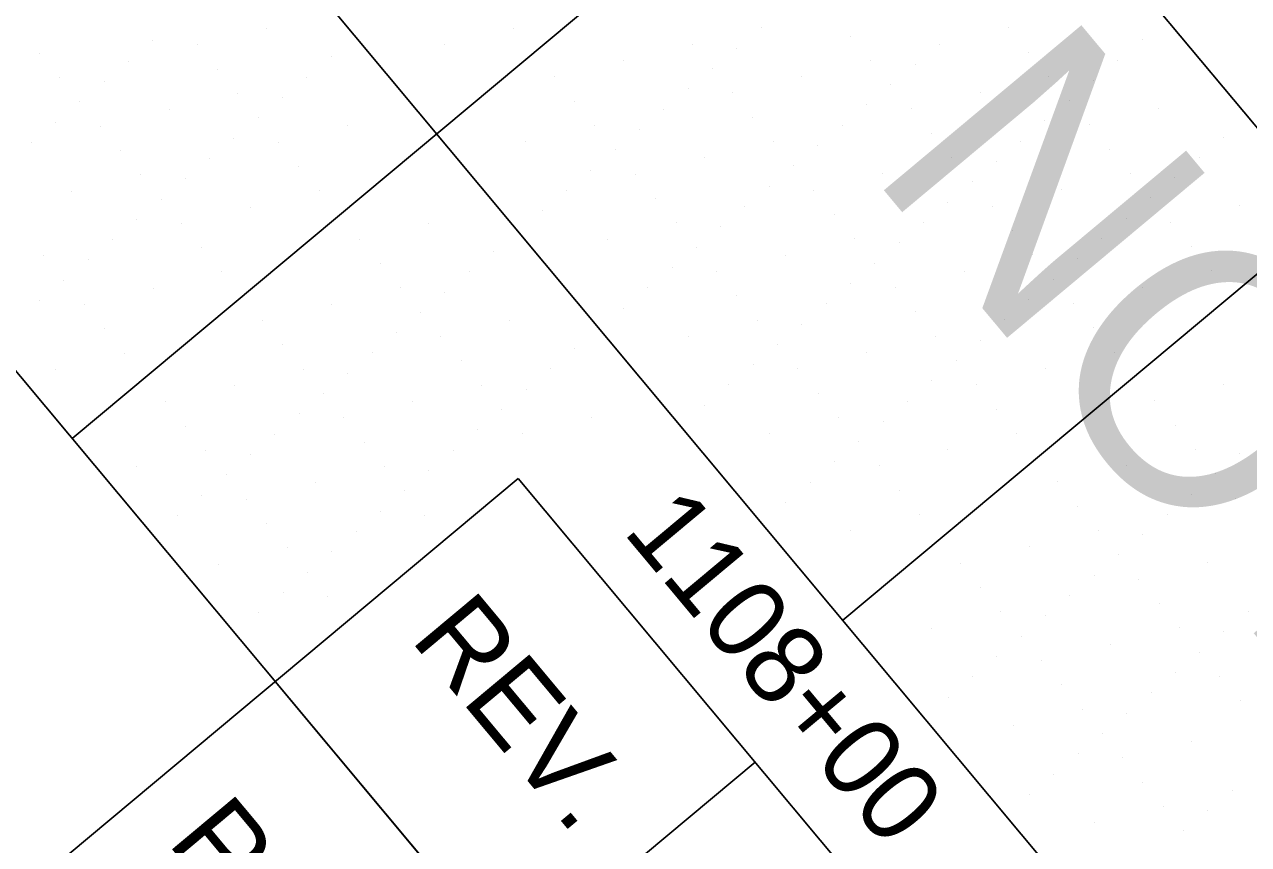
# Model space of a CAD drawing. Extents: x 2042995 to 2043795, y 305365 to 306249.
# Drawn here: x 2043381.75 to 2043420.4, y 305583.24 to 305609.13 of the extents above; entities that cross this region are included whole.
import ezdxf

# ---------------------------------------------------------------- set-up
doc = ezdxf.new("R2010")
doc.units = 0
for name, color, linetype in [('BR_BORDER LINES', 7, 'Continuous'), ('BR_CONCRETE', 7, 'Continuous'), ('BR_GRID DOTS', 7, 'Continuous'), ('BR_GRID LINES', 7, 'Continuous'), ('BR_TEXT', 7, 'Continuous')]:
    doc.layers.add(name, color=color, linetype=linetype)

msp = doc.modelspace()

# ---------------------------------------------------------------- linework, layer by layer
at = {"layer": 'BR_BORDER LINES'}
for p, q in [((2043360.173, 305623.692), (2043416.369, 305556.406)), ((2043355.121, 305559.541), (2043397.335, 305594.797)), ((2043397.335, 305594.797), (2043493.488, 305479.669)), ((2043389.659, 305588.387), (2043416.369, 305556.407)), ((2043404.813, 305585.843), (2043381.788, 305566.612))]:
    msp.add_line(p, q, dxfattribs=at)
at = {"layer": 'BR_CONCRETE'}
msp.add_spline([(2043139.109, 306017.548), (2043148.199, 306007.16), (2043160.233, 305993.368), (2043172.245, 305979.557), (2043184.234, 305965.727), (2043196.201, 305951.879), (2043208.145, 305938.012), (2043220.067, 305924.126), (2043231.966, 305910.221), (2043243.843, 305896.297), (2043255.698, 305882.355), (2043267.529, 305868.394), (2043279.339, 305854.414), (2043291.126, 305840.415), (2043302.89, 305826.398), (2043314.632, 305812.361), (2043326.352, 305798.306), (2043338.049, 305784.233), (2043349.724, 305770.14), (2043361.376, 305756.029), (2043373.005, 305741.899), (2043384.613, 305727.75), (2043396.197, 305713.582), (2043407.76, 305699.396), (2043419.299, 305685.191), (2043430.817, 305670.967), (2043442.311, 305656.724), (2043453.784, 305642.463), (2043465.234, 305628.182), (2043476.661, 305613.883), (2043488.066, 305599.566), (2043499.448, 305585.229), (2043510.808, 305570.874), (2043522.146, 305556.5), (2043533.461, 305542.107), (2043544.753, 305527.695), (2043547.219, 305524.543)], degree=3, dxfattribs=at)
at = {"layer": 'BR_GRID DOTS'}
for p, q in [((2043389.381, 305609), (2043389.381, 305609)), ((2043397.192, 305609.008), (2043397.192, 305609.008)), ((2043405.002, 305609.017), (2043405.002, 305609.017)), ((2043412.812, 305609.025), (2043412.812, 305609.025)), ((2043385.797, 305608.612), (2043385.797, 305608.612)), ((2043392.198, 305608.747), (2043392.198, 305608.747)), ((2043407.819, 305608.764), (2043407.819, 305608.764)), ((2043410.636, 305608.511), (2043410.636, 305608.511)), ((2043417.038, 305608.646), (2043417.038, 305608.646)), ((2043382.212, 305608.224), (2043382.212, 305608.224)), ((2043387.205, 305608.485), (2043387.205, 305608.485)), ((2043395.016, 305608.494), (2043395.016, 305608.494)), ((2043402.826, 305608.502), (2043402.826, 305608.502)), ((2043404.234, 305608.376), (2043404.234, 305608.376)), ((2043413.453, 305608.258), (2043413.453, 305608.258)), ((2043385.029, 305607.971), (2043385.029, 305607.971)), ((2043391.431, 305608.106), (2043391.431, 305608.106)), ((2043400.65, 305607.988), (2043400.65, 305607.988)), ((2043408.46, 305607.996), (2043408.46, 305607.996)), ((2043409.869, 305607.87), (2043409.869, 305607.87)), ((2043416.27, 305608.005), (2043416.27, 305608.005)), ((2043382.853, 305607.456), (2043382.853, 305607.456)), ((2043387.846, 305607.718), (2043387.846, 305607.718)), ((2043390.663, 305607.465), (2043390.663, 305607.465)), ((2043398.474, 305607.473), (2043398.474, 305607.473)), ((2043403.467, 305607.735), (2043403.467, 305607.735)), ((2043406.284, 305607.482), (2043406.284, 305607.482)), ((2043414.094, 305607.49), (2043414.094, 305607.49)), ((2043415.503, 305607.364), (2043415.503, 305607.364)), ((2043384.262, 305607.33), (2043384.262, 305607.33)), ((2043402.699, 305607.094), (2043402.699, 305607.094)), ((2043404.108, 305606.967), (2043404.108, 305606.967)), ((2043409.101, 305607.229), (2043409.101, 305607.229)), ((2043411.918, 305606.976), (2043411.918, 305606.976)), ((2043383.494, 305606.689), (2043383.494, 305606.689)), ((2043388.487, 305606.95), (2043388.487, 305606.95)), ((2043389.896, 305606.824), (2043389.896, 305606.824)), ((2043399.115, 305606.706), (2043399.115, 305606.706)), ((2043408.334, 305606.588), (2043408.334, 305606.588)), ((2043414.735, 305606.723), (2043414.735, 305606.723)), ((2043386.311, 305606.436), (2043386.311, 305606.436)), ((2043401.932, 305606.453), (2043401.932, 305606.453)), ((2043404.749, 305606.2), (2043404.749, 305606.2)), ((2043409.742, 305606.461), (2043409.742, 305606.461)), ((2043417.552, 305606.47), (2043417.552, 305606.47)), ((2043420.369, 305606.217), (2043420.369, 305606.217)), ((2043382.727, 305606.048), (2043382.727, 305606.048)), ((2043384.135, 305605.921), (2043384.135, 305605.921)), ((2043389.128, 305606.183), (2043389.128, 305606.183)), ((2043391.945, 305605.93), (2043391.945, 305605.93)), ((2043399.756, 305605.938), (2043399.756, 305605.938)), ((2043401.164, 305605.812), (2043401.164, 305605.812)), ((2043407.566, 305605.947), (2043407.566, 305605.947)), ((2043413.968, 305606.082), (2043413.968, 305606.082)), ((2043415.376, 305605.955), (2043415.376, 305605.955)), ((2043388.361, 305605.542), (2043388.361, 305605.542)), ((2043397.58, 305605.424), (2043397.58, 305605.424)), ((2043405.39, 305605.432), (2043405.39, 305605.432)), ((2043410.383, 305605.694), (2043410.383, 305605.694)), ((2043413.2, 305605.441), (2043413.2, 305605.441)), ((2043419.602, 305605.576), (2043419.602, 305605.576)), ((2043381.959, 305605.406), (2043381.959, 305605.406)), ((2043384.776, 305605.153), (2043384.776, 305605.153)), ((2043389.769, 305605.415), (2043389.769, 305605.415)), ((2043400.397, 305605.171), (2043400.397, 305605.171)), ((2043406.798, 305605.306), (2043406.798, 305605.306)), ((2043416.017, 305605.188), (2043416.017, 305605.188)), ((2043387.593, 305604.901), (2043387.593, 305604.901)), ((2043390.41, 305604.648), (2043390.41, 305604.648)), ((2043403.214, 305604.918), (2043403.214, 305604.918)), ((2043406.031, 305604.665), (2043406.031, 305604.665)), ((2043411.024, 305604.926), (2043411.024, 305604.926)), ((2043412.433, 305604.8), (2043412.433, 305604.8)), ((2043418.834, 305604.935), (2043418.834, 305604.935)), ((2043385.417, 305604.386), (2043385.417, 305604.386)), ((2043386.826, 305604.259), (2043386.826, 305604.259)), ((2043399.629, 305604.53), (2043399.629, 305604.53)), ((2043401.038, 305604.403), (2043401.038, 305604.403)), ((2043408.848, 305604.412), (2043408.848, 305604.412)), ((2043416.658, 305604.42), (2043416.658, 305604.42)), ((2043418.067, 305604.294), (2043418.067, 305604.294)), ((2043383.241, 305603.871), (2043383.241, 305603.871)), ((2043391.051, 305603.88), (2043391.051, 305603.88)), ((2043398.862, 305603.889), (2043398.862, 305603.889)), ((2043405.263, 305604.024), (2043405.263, 305604.024)), ((2043406.672, 305603.897), (2043406.672, 305603.897)), ((2043411.665, 305604.159), (2043411.665, 305604.159)), ((2043414.482, 305603.906), (2043414.482, 305603.906)), ((2043386.058, 305603.618), (2043386.058, 305603.618)), ((2043401.679, 305603.636), (2043401.679, 305603.636)), ((2043410.898, 305603.518), (2043410.898, 305603.518)), ((2043417.299, 305603.653), (2043417.299, 305603.653)), ((2043388.875, 305603.365), (2043388.875, 305603.365)), ((2043398.094, 305603.248), (2043398.094, 305603.248)), ((2043404.496, 305603.383), (2043404.496, 305603.383)), ((2043407.313, 305603.13), (2043407.313, 305603.13)), ((2043412.306, 305603.391), (2043412.306, 305603.391)), ((2043420.116, 305603.4), (2043420.116, 305603.4)), ((2043385.291, 305602.977), (2043385.291, 305602.977)), ((2043386.699, 305602.851), (2043386.699, 305602.851)), ((2043394.51, 305602.86), (2043394.51, 305602.86)), ((2043402.32, 305602.868), (2043402.32, 305602.868)), ((2043403.728, 305602.742), (2043403.728, 305602.742)), ((2043410.13, 305602.877), (2043410.13, 305602.877)), ((2043416.532, 305603.012), (2043416.532, 305603.012)), ((2043417.94, 305602.885), (2043417.94, 305602.885)), ((2043384.523, 305602.336), (2043384.523, 305602.336)), ((2043392.334, 305602.345), (2043392.334, 305602.345)), ((2043397.327, 305602.607), (2043397.327, 305602.607)), ((2043400.144, 305602.354), (2043400.144, 305602.354)), ((2043407.954, 305602.362), (2043407.954, 305602.362)), ((2043412.947, 305602.624), (2043412.947, 305602.624)), ((2043415.764, 305602.371), (2043415.764, 305602.371)), ((2043387.34, 305602.083), (2043387.34, 305602.083)), ((2043396.559, 305601.965), (2043396.559, 305601.965)), ((2043402.961, 305602.101), (2043402.961, 305602.101)), ((2043409.363, 305602.236), (2043409.363, 305602.236)), ((2043418.581, 305602.118), (2043418.581, 305602.118)), ((2043382.347, 305601.822), (2043382.347, 305601.822)), ((2043383.756, 305601.695), (2043383.756, 305601.695)), ((2043392.975, 305601.577), (2043392.975, 305601.577)), ((2043405.778, 305601.848), (2043405.778, 305601.848)), ((2043408.595, 305601.595), (2043408.595, 305601.595)), ((2043413.588, 305601.856), (2043413.588, 305601.856)), ((2043414.997, 305601.73), (2043414.997, 305601.73)), ((2043387.981, 305601.316), (2043387.981, 305601.316)), ((2043395.792, 305601.324), (2043395.792, 305601.324)), ((2043402.193, 305601.46), (2043402.193, 305601.46)), ((2043403.602, 305601.333), (2043403.602, 305601.333)), ((2043411.412, 305601.342), (2043411.412, 305601.342)), ((2043419.222, 305601.35), (2043419.222, 305601.35)), ((2043382.988, 305601.054), (2043382.988, 305601.054)), ((2043385.805, 305600.801), (2043385.805, 305600.801)), ((2043393.616, 305600.81), (2043393.616, 305600.81)), ((2043401.426, 305600.818), (2043401.426, 305600.818)), ((2043407.828, 305600.954), (2043407.828, 305600.954)), ((2043409.236, 305600.827), (2043409.236, 305600.827)), ((2043414.229, 305601.089), (2043414.229, 305601.089)), ((2043417.046, 305600.836), (2043417.046, 305600.836)), ((2043382.221, 305600.413), (2043382.221, 305600.413)), ((2043395.024, 305600.683), (2043395.024, 305600.683)), ((2043395.024, 305600.683), (2043395.024, 305600.683)), ((2043404.243, 305600.566), (2043404.243, 305600.566)), ((2043413.462, 305600.448), (2043413.462, 305600.448)), ((2043383.629, 305600.287), (2043383.629, 305600.287)), ((2043391.44, 305600.295), (2043391.44, 305600.295)), ((2043394.257, 305600.042), (2043394.257, 305600.042)), ((2043400.658, 305600.177), (2043400.658, 305600.177)), ((2043407.06, 305600.313), (2043407.06, 305600.313)), ((2043409.877, 305600.06), (2043409.877, 305600.06)), ((2043414.87, 305600.321), (2043414.87, 305600.321)), ((2043389.263, 305599.781), (2043389.263, 305599.781)), ((2043397.074, 305599.789), (2043397.074, 305599.789)), ((2043404.884, 305599.798), (2043404.884, 305599.798)), ((2043406.292, 305599.671), (2043406.292, 305599.671)), ((2043412.694, 305599.807), (2043412.694, 305599.807)), ((2043384.27, 305599.519), (2043384.27, 305599.519)), ((2043393.489, 305599.401), (2043393.489, 305599.401)), ((2043394.898, 305599.275), (2043394.898, 305599.275)), ((2043399.891, 305599.536), (2043399.891, 305599.536)), ((2043402.708, 305599.283), (2043402.708, 305599.283)), ((2043410.518, 305599.292), (2043410.518, 305599.292)), ((2043415.511, 305599.554), (2043415.511, 305599.554)), ((2043389.904, 305599.013), (2043389.904, 305599.013)), ((2043399.123, 305598.895), (2043399.123, 305598.895)), ((2043405.525, 305599.03), (2043405.525, 305599.03)), ((2043411.927, 305599.166), (2043411.927, 305599.166)), ((2043384.911, 305598.752), (2043384.911, 305598.752)), ((2043392.722, 305598.76), (2043392.722, 305598.76)), ((2043395.539, 305598.507), (2043395.539, 305598.507)), ((2043408.342, 305598.777), (2043408.342, 305598.777)), ((2043411.159, 305598.524), (2043411.159, 305598.524)), ((2043416.152, 305598.786), (2043416.152, 305598.786)), ((2043382.735, 305598.237), (2043382.735, 305598.237)), ((2043390.546, 305598.246), (2043390.546, 305598.246)), ((2043391.954, 305598.119), (2043391.954, 305598.119)), ((2043398.356, 305598.254), (2043398.356, 305598.254)), ((2043404.757, 305598.389), (2043404.757, 305598.389)), ((2043406.166, 305598.263), (2043406.166, 305598.263)), ((2043413.976, 305598.272), (2043413.976, 305598.272)), ((2043388.369, 305597.731), (2043388.369, 305597.731)), ((2043396.18, 305597.74), (2043396.18, 305597.74)), ((2043403.99, 305597.748), (2043403.99, 305597.748)), ((2043410.392, 305597.883), (2043410.392, 305597.883)), ((2043411.8, 305597.757), (2043411.8, 305597.757)), ((2043419.61, 305597.766), (2043419.61, 305597.766)), ((2043391.187, 305597.478), (2043391.187, 305597.478)), ((2043397.588, 305597.613), (2043397.588, 305597.613)), ((2043397.588, 305597.613), (2043397.588, 305597.613)), ((2043406.807, 305597.495), (2043406.807, 305597.495)), ((2043386.193, 305597.217), (2043386.193, 305597.217)), ((2043394.004, 305597.225), (2043394.004, 305597.225)), ((2043396.821, 305596.972), (2043396.821, 305596.972)), ((2043403.222, 305597.107), (2043403.222, 305597.107)), ((2043409.624, 305597.242), (2043409.624, 305597.242)), ((2043412.441, 305596.989), (2043412.441, 305596.989)), ((2043417.434, 305597.251), (2043417.434, 305597.251)), ((2043390.419, 305596.837), (2043390.419, 305596.837)), ((2043391.828, 305596.711), (2043391.828, 305596.711)), ((2043399.638, 305596.719), (2043399.638, 305596.719)), ((2043407.448, 305596.728), (2043407.448, 305596.728)), ((2043408.857, 305596.601), (2043408.857, 305596.601)), ((2043386.834, 305596.449), (2043386.834, 305596.449)), ((2043389.652, 305596.196), (2043389.652, 305596.196)), ((2043396.053, 305596.331), (2043396.053, 305596.331)), ((2043397.462, 305596.205), (2043397.462, 305596.205)), ((2043402.455, 305596.466), (2043402.455, 305596.466)), ((2043405.272, 305596.213), (2043405.272, 305596.213)), ((2043413.082, 305596.222), (2043413.082, 305596.222)), ((2043418.075, 305596.483), (2043418.075, 305596.483)), ((2043392.469, 305595.943), (2043392.469, 305595.943)), ((2043408.089, 305595.96), (2043408.089, 305595.96)), ((2043387.475, 305595.682), (2043387.475, 305595.682)), ((2043388.884, 305595.555), (2043388.884, 305595.555)), ((2043395.286, 305595.69), (2043395.286, 305595.69)), ((2043410.906, 305595.707), (2043410.906, 305595.707)), ((2043418.716, 305595.716), (2043418.716, 305595.716)), ((2043420.125, 305595.589), (2043420.125, 305595.589)), ((2043385.299, 305595.167), (2043385.299, 305595.167)), ((2043393.11, 305595.176), (2043393.11, 305595.176)), ((2043394.518, 305595.049), (2043394.518, 305595.049)), ((2043407.322, 305595.319), (2043407.322, 305595.319)), ((2043408.73, 305595.193), (2043408.73, 305595.193)), ((2043416.54, 305595.201), (2043416.54, 305595.201)), ((2043388.116, 305594.914), (2043388.116, 305594.914)), ((2043390.934, 305594.661), (2043390.934, 305594.661)), ((2043406.554, 305594.678), (2043406.554, 305594.678)), ((2043414.364, 305594.687), (2043414.364, 305594.687)), ((2043419.357, 305594.948), (2043419.357, 305594.948)), ((2043387.349, 305594.273), (2043387.349, 305594.273)), ((2043393.751, 305594.408), (2043393.751, 305594.408)), ((2043409.371, 305594.425), (2043409.371, 305594.425)), ((2043418.59, 305594.307), (2043418.59, 305594.307)), ((2043388.757, 305594.147), (2043388.757, 305594.147)), ((2043405.787, 305594.037), (2043405.787, 305594.037)), ((2043415.005, 305593.919), (2043415.005, 305593.919)), ((2043419.998, 305594.181), (2043419.998, 305594.181)), ((2043386.581, 305593.632), (2043386.581, 305593.632)), ((2043392.983, 305593.767), (2043392.983, 305593.767)), ((2043394.392, 305593.641), (2043394.392, 305593.641)), ((2043410.012, 305593.658), (2043410.012, 305593.658)), ((2043417.822, 305593.666), (2043417.822, 305593.666)), ((2043389.399, 305593.379), (2043389.399, 305593.379)), ((2043392.216, 305593.126), (2043392.216, 305593.126)), ((2043405.019, 305593.396), (2043405.019, 305593.396)), ((2043407.836, 305593.143), (2043407.836, 305593.143)), ((2043415.646, 305593.152), (2043415.646, 305593.152)), ((2043417.055, 305593.025), (2043417.055, 305593.025)), ((2043390.04, 305592.612), (2043390.04, 305592.612)), ((2043391.448, 305592.485), (2043391.448, 305592.485)), ((2043413.47, 305592.637), (2043413.47, 305592.637)), ((2043416.287, 305592.384), (2043416.287, 305592.384)), ((2043387.863, 305592.097), (2043387.863, 305592.097)), ((2043411.294, 305592.123), (2043411.294, 305592.123)), ((2043419.104, 305592.131), (2043419.104, 305592.131)), ((2043390.681, 305591.844), (2043390.681, 305591.844)), ((2043415.52, 305591.743), (2043415.52, 305591.743)), ((2043416.928, 305591.617), (2043416.928, 305591.617)), ((2043389.913, 305591.203), (2043389.913, 305591.203)), ((2043411.935, 305591.355), (2043411.935, 305591.355)), ((2043391.322, 305591.077), (2043391.322, 305591.077)), ((2043414.752, 305591.102), (2043414.752, 305591.102)), ((2043417.569, 305590.849), (2043417.569, 305590.849)), ((2043389.146, 305590.562), (2043389.146, 305590.562)), ((2043412.576, 305590.588), (2043412.576, 305590.588)), ((2043413.985, 305590.461), (2043413.985, 305590.461)), ((2043420.386, 305590.596), (2043420.386, 305590.596)), ((2043410.4, 305590.073), (2043410.4, 305590.073)), ((2043418.21, 305590.082), (2043418.21, 305590.082)), ((2043413.217, 305589.82), (2043413.217, 305589.82)), ((2043419.619, 305589.955), (2043419.619, 305589.955)), ((2043416.034, 305589.567), (2043416.034, 305589.567)), ((2043418.851, 305589.314), (2043418.851, 305589.314)), ((2043412.45, 305589.179), (2043412.45, 305589.179)), ((2043413.858, 305589.053), (2043413.858, 305589.053)), ((2043411.682, 305588.538), (2043411.682, 305588.538)), ((2043418.084, 305588.673), (2043418.084, 305588.673)), ((2043419.492, 305588.547), (2043419.492, 305588.547)), ((2043414.499, 305588.285), (2043414.499, 305588.285)), ((2043417.316, 305588.032), (2043417.316, 305588.032)), ((2043410.915, 305587.897), (2043410.915, 305587.897)), ((2043420.134, 305587.779), (2043420.134, 305587.779)), ((2043410.147, 305587.256), (2043410.147, 305587.256)), ((2043415.14, 305587.518), (2043415.14, 305587.518)), ((2043416.549, 305587.391), (2043416.549, 305587.391)), ((2043412.964, 305587.003), (2043412.964, 305587.003)), ((2043415.781, 305586.75), (2043415.781, 305586.75)), ((2043418.598, 305586.497), (2043418.598, 305586.497)), ((2043415.014, 305586.109), (2043415.014, 305586.109)), ((2043416.422, 305585.983), (2043416.422, 305585.983)), ((2043414.246, 305585.468), (2043414.246, 305585.468)), ((2043417.063, 305585.215), (2043417.063, 305585.215)), ((2043419.881, 305584.962), (2043419.881, 305584.962)), ((2043413.479, 305584.827), (2043413.479, 305584.827)), ((2043412.711, 305584.186), (2043412.711, 305584.186)), ((2043417.704, 305584.448), (2043417.704, 305584.448)), ((2043419.113, 305584.321), (2043419.113, 305584.321)), ((2043415.528, 305583.933), (2043415.528, 305583.933)), ((2043418.345, 305583.68), (2043418.345, 305583.68))]:
    msp.add_line(p, q, dxfattribs=at)
at = {"layer": 'BR_GRID LINES'}
for p, q in [((2043179.344, 305894.804), (2043523.36, 305482.903)), ((2043163.993, 305881.983), (2043508.01, 305470.082)), ((2043502.215, 305695.42), (2043383.25, 305596.061)), ((2043515.036, 305680.07), (2043407.583, 305590.326))]:
    msp.add_line(p, q, dxfattribs=at)

# ---------------------------------------------------------------- texts
at = {"layer": 'BR_TEXT'}
for s, height, p in [('NOT FOR CONSTRUCTION', 8.12508, (2043408.31, 305604.579)), ('1108+00', 2.5, (2043400.609, 305593.119)), ('REV.', 2.6, (2043393.898, 305589.72)), ('REV.', 2.6, (2043386.223, 305583.31))]:
    msp.add_text(s, height=height, rotation=309.8684, dxfattribs=at).set_placement(p)

doc.saveas('drawing.dxf')
